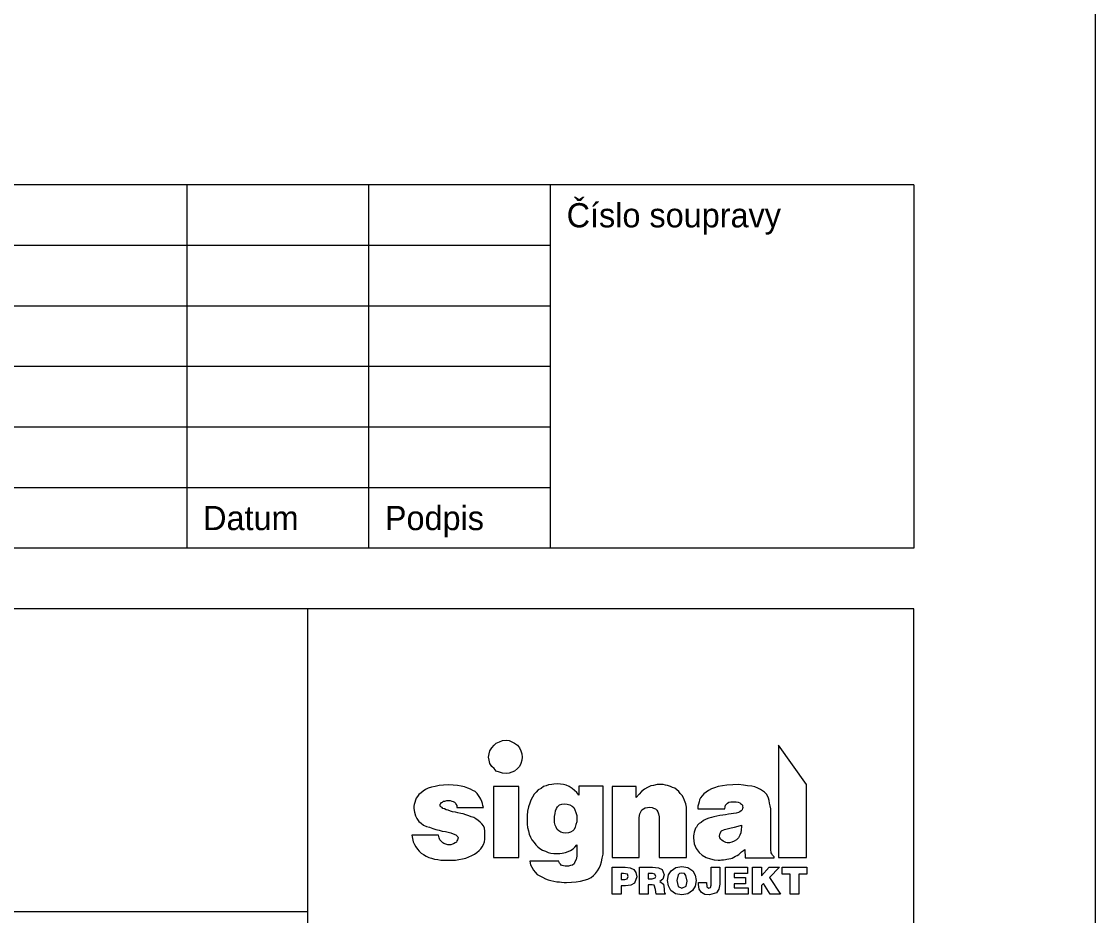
# Model space of a CAD drawing. Extents: x -790471 to -790261, y -984666 to -984369.
# Drawn here: x -790349.2 to -790260.6, y -984590.9 to -984517.1 of the extents above; entities that cross this region are included whole.
import ezdxf

# ---------------------------------------------------------------- set-up
doc = ezdxf.new("R2010")
doc.units = 0
for name, color, linetype in [('Info o rozpiskách', 7, 'Continuous'), ('popis', 7, 'Continuous'), ('Ramečky', 7, 'Continuous'), ('Rámečky-tisk', 7, 'Continuous'), ('Text', 7, 'Continuous')]:
    doc.layers.add(name, color=color, linetype=linetype)

msp = doc.modelspace()

# ---------------------------------------------------------------- linework, layer by layer
at = {"layer": 'Info o rozpiskách'}
for points in [[(-790309.246, -984576.456), (-790308.985, -984576.475), (-790308.761, -984576.568), (-790308.537, -984576.699), (-790308.294, -984576.867), (-790308.145, -984577.072), (-790308.033, -984577.315), (-790307.94, -984577.575), (-790307.921, -984577.837), (-790307.94, -984578.098), (-790308.033, -984578.378), (-790308.145, -984578.62), (-790308.294, -984578.788), (-790308.537, -984578.994), (-790308.761, -984579.087), (-790308.985, -984579.18), (-790309.246, -984579.199), (-790309.545, -984579.18), (-790309.787, -984579.087), (-790310.048, -984578.994), (-790310.235, -984578.788), (-790310.402, -984578.62), (-790310.571, -984578.378), (-790310.645, -984578.098), (-790310.701, -984577.837), (-790310.645, -984577.575), (-790310.571, -984577.315), (-790310.402, -984577.072), (-790310.235, -984576.867), (-790310.048, -984576.699), (-790309.787, -984576.568), (-790309.545, -984576.475), (-790309.246, -984576.456)], [(-790300.477, -984586.941), (-790299.414, -984586.941), (-790299.004, -984586.979), (-790298.705, -984587.128), (-790298.518, -984587.371), (-790298.462, -984587.725), (-790298.649, -984588.247), (-790298.948, -984588.416), (-790299.377, -984588.471), (-790299.75, -984588.471), (-790299.75, -984589.162), (-790300.477, -984589.162), (-790300.477, -984586.941)], [(-790299.75, -984587.445), (-790299.75, -984587.949), (-790299.432, -984587.949), (-790299.246, -984587.893), (-790299.153, -984587.688), (-790299.227, -984587.52), (-790299.545, -984587.445), (-790299.75, -984587.445)], [(-790298.238, -984586.941), (-790297.156, -984586.941), (-790296.672, -984586.979), (-790296.354, -984587.128), (-790296.186, -984587.576), (-790296.298, -984587.93), (-790296.559, -984588.117), (-790296.242, -984588.341), (-790296.186, -984588.714), (-790296.186, -984588.882), (-790296.168, -984589.05), (-790296.111, -984589.106), (-790296.111, -984589.162), (-790296.858, -984589.162), (-790296.896, -984588.769), (-790297.026, -984588.416), (-790297.175, -984588.396), (-790297.399, -984588.378), (-790297.511, -984588.378), (-790297.511, -984589.162), (-790298.238, -984589.162), (-790298.238, -984586.941)], [(-790297.511, -984587.445), (-790297.511, -984587.893), (-790297.194, -984587.893), (-790296.932, -984587.819), (-790296.876, -984587.688), (-790296.951, -984587.52), (-790297.156, -984587.445), (-790297.511, -984587.445)], [(-790294.731, -984586.885), (-790294.227, -984586.96), (-790293.835, -984587.221), (-790293.63, -984587.595), (-790293.556, -984588.023), (-790293.63, -984588.49), (-790293.854, -984588.863), (-790294.227, -984589.124), (-790294.731, -984589.217), (-790295.253, -984589.124), (-790295.645, -984588.844), (-790295.832, -984588.471), (-790295.907, -984588.023), (-790295.832, -984587.576), (-790295.608, -984587.221), (-790295.235, -984586.96), (-790294.731, -984586.885)], [(-790294.731, -984587.427), (-790294.918, -984587.464), (-790295.048, -984587.576), (-790295.16, -984588.042), (-790295.048, -984588.527), (-790294.731, -984588.676), (-790294.376, -984588.49), (-790294.283, -984588.079), (-790294.396, -984587.613), (-790294.525, -984587.464), (-790294.731, -984587.427)], [(-790292.325, -984586.941), (-790291.597, -984586.941), (-790291.597, -984588.322), (-790291.672, -984588.751), (-790291.877, -984589.05), (-790292.456, -984589.217), (-790292.829, -984589.18), (-790293.108, -984589.031), (-790293.295, -984588.751), (-790293.37, -984588.359), (-790293.351, -984588.192), (-790292.698, -984588.192), (-790292.661, -984588.565), (-790292.512, -984588.676), (-790292.381, -984588.602), (-790292.325, -984588.416), (-790292.325, -984586.941)], [(-790291.131, -984586.941), (-790289.321, -984586.941), (-790289.321, -984587.445), (-790290.404, -984587.445), (-790290.404, -984587.781), (-790289.489, -984587.781), (-790289.489, -984588.303), (-790290.404, -984588.303), (-790290.404, -984588.639), (-790289.266, -984588.639), (-790289.266, -984589.162), (-790291.131, -984589.162), (-790291.131, -984586.941)], [(-790288.911, -984586.941), (-790288.165, -984586.941), (-790288.165, -984587.651), (-790287.531, -984586.941), (-790286.672, -984586.941), (-790287.493, -984587.781), (-790286.579, -984589.162), (-790287.456, -984589.162), (-790287.997, -984588.285), (-790288.165, -984588.452), (-790288.165, -984589.162), (-790288.911, -984589.162), (-790288.911, -984586.941)], [(-790286.467, -984586.941), (-790284.414, -984586.941), (-790284.414, -984587.52), (-790285.068, -984587.52), (-790285.068, -984589.162), (-790285.796, -984589.162), (-790285.796, -984587.52), (-790286.467, -984587.52), (-790286.467, -984586.941)]]:
    msp.add_lwpolyline(points, dxfattribs=at)
at = {"layer": 'popis'}
for points in [[(-790286.765, -984576.867), (-790286.765, -984586.139), (-790284.452, -984586.139), (-790284.452, -984580.113), (-790286.765, -984576.867)], [(-790313.294, -984582.016), (-790311.093, -984582.016), (-790311.149, -984581.83), (-790311.187, -984581.661), (-790311.242, -984581.494), (-790311.316, -984581.326), (-790311.41, -984581.177), (-790311.522, -984581.009), (-790311.634, -984580.86), (-790311.802, -984580.691), (-790311.97, -984580.598), (-790312.175, -984580.486), (-790312.399, -984580.393), (-790312.66, -984580.299), (-790312.94, -984580.244), (-790313.257, -984580.188), (-790313.612, -984580.15), (-790314.003, -984580.132), (-790314.395, -984580.15), (-790314.768, -984580.188), (-790315.085, -984580.262), (-790315.402, -984580.319), (-790315.664, -984580.412), (-790315.888, -984580.523), (-790316.074, -984580.654), (-790316.261, -984580.785), (-790316.429, -984580.934), (-790316.541, -984581.084), (-790316.653, -984581.233), (-790316.709, -984581.4), (-790316.784, -984581.587), (-790316.82, -984581.755), (-790316.858, -984581.885), (-790316.858, -984582.091), (-790316.802, -984582.389), (-790316.709, -984582.688), (-790316.615, -984582.912), (-790316.429, -984583.154), (-790316.261, -984583.285), (-790316.056, -984583.453), (-790315.813, -984583.565), (-790315.552, -984583.639), (-790315.291, -984583.733), (-790315.029, -984583.807), (-790314.768, -984583.882), (-790314.507, -984583.957), (-790314.246, -984583.993), (-790314.022, -984584.031), (-790313.798, -984584.087), (-790313.593, -984584.181), (-790313.388, -984584.255), (-790313.294, -984584.33), (-790313.22, -984584.423), (-790313.201, -984584.516), (-790313.239, -984584.684), (-790313.294, -984584.758), (-790313.332, -984584.852), (-790313.444, -984584.927), (-790313.574, -984585.001), (-790313.667, -984585.038), (-790313.798, -984585.076), (-790313.929, -984585.076), (-790314.06, -984585.076), (-790314.209, -984585.038), (-790314.377, -984584.982), (-790314.47, -984584.927), (-790314.601, -984584.796), (-790314.694, -984584.684), (-790314.768, -984584.498), (-790314.825, -984584.274), (-790317.007, -984584.274), (-790316.97, -984584.572), (-790316.895, -984584.833), (-790316.802, -984585.057), (-790316.69, -984585.244), (-790316.56, -984585.43), (-790316.41, -984585.598), (-790316.242, -984585.766), (-790316.056, -984585.896), (-790315.832, -984586.009), (-790315.608, -984586.12), (-790315.384, -984586.195), (-790315.142, -984586.269), (-790314.861, -984586.289), (-790314.619, -984586.344), (-790314.377, -984586.363), (-790314.06, -984586.363), (-790313.742, -984586.344), (-790313.425, -984586.344), (-790313.126, -984586.289), (-790312.828, -984586.233), (-790312.549, -984586.176), (-790312.306, -984586.083), (-790312.063, -984585.953), (-790311.858, -984585.859), (-790311.653, -984585.729), (-790311.466, -984585.561), (-790311.336, -984585.412), (-790311.205, -984585.244), (-790311.093, -984585.057), (-790311.018, -984584.833), (-790310.999, -984584.609), (-790310.999, -984584.385), (-790310.999, -984584.33), (-790310.999, -984584.274), (-790310.999, -984584.217), (-790310.999, -984584.161), (-790310.999, -984584.087), (-790310.999, -984584.031), (-790310.999, -984583.993), (-790310.999, -984583.957), (-790311.018, -984583.714), (-790311.112, -984583.527), (-790311.242, -984583.341), (-790311.391, -984583.21), (-790311.54, -984583.079), (-790311.727, -984582.93), (-790311.895, -984582.837), (-790312.119, -984582.762), (-790312.325, -984582.688), (-790312.549, -984582.613), (-790312.772, -984582.538), (-790312.977, -984582.501), (-790313.22, -984582.445), (-790313.425, -984582.389), (-790313.649, -984582.352), (-790313.836, -984582.296), (-790314.022, -984582.222), (-790314.19, -984582.184), (-790314.32, -984582.109), (-790314.451, -984582.072), (-790314.526, -984582.016), (-790314.637, -984581.941), (-790314.675, -984581.885), (-790314.675, -984581.811), (-790314.675, -984581.736), (-790314.637, -984581.661), (-790314.563, -984581.587), (-790314.488, -984581.55), (-790314.414, -984581.475), (-790314.283, -984581.475), (-790314.134, -984581.437), (-790314.003, -984581.437), (-790313.854, -984581.437), (-790313.723, -984581.475), (-790313.612, -984581.494), (-790313.499, -984581.55), (-790313.425, -984581.643), (-790313.388, -984581.736), (-790313.313, -984581.848), (-790313.294, -984582.016)], [(-790310.272, -984580.262), (-790310.272, -984586.139), (-790308.183, -984586.139), (-790308.183, -984580.262), (-790310.272, -984580.262)], [(-790303.239, -984580.244), (-790303.239, -984580.971), (-790303.407, -984580.766), (-790303.593, -984580.598), (-790303.798, -984580.43), (-790304.041, -984580.281), (-790304.283, -984580.169), (-790304.507, -984580.113), (-790304.75, -984580.075), (-790305.029, -984580.057), (-790305.291, -984580.075), (-790305.477, -984580.095), (-790305.739, -984580.132), (-790305.925, -984580.225), (-790306.149, -984580.281), (-790306.354, -984580.43), (-790306.578, -984580.542), (-790306.764, -984580.729), (-790306.914, -984580.915), (-790307.063, -984581.158), (-790307.194, -984581.4), (-790307.287, -984581.643), (-790307.399, -984581.96), (-790307.474, -984582.296), (-790307.511, -984582.669), (-790307.511, -984583.061), (-790307.511, -984583.378), (-790307.474, -984583.658), (-790307.399, -984583.919), (-790307.325, -984584.199), (-790307.231, -984584.441), (-790307.101, -984584.684), (-790306.932, -984584.889), (-790306.783, -984585.076), (-790306.615, -984585.244), (-790306.447, -984585.393), (-790306.224, -984585.523), (-790306, -984585.617), (-790305.776, -984585.71), (-790305.533, -984585.766), (-790305.291, -984585.803), (-790305.029, -984585.803), (-790304.805, -984585.803), (-790304.601, -984585.766), (-790304.339, -984585.729), (-790304.115, -984585.636), (-790303.91, -984585.543), (-790303.705, -984585.412), (-790303.556, -984585.281), (-790303.388, -984585.095), (-790303.388, -984585.636), (-790303.388, -984586.027), (-790303.462, -984586.289), (-790303.556, -984586.493), (-790303.631, -984586.643), (-790303.761, -984586.755), (-790303.91, -984586.792), (-790304.078, -984586.848), (-790304.264, -984586.848), (-790304.358, -984586.848), (-790304.488, -984586.83), (-790304.601, -984586.792), (-790304.694, -984586.755), (-790304.75, -984586.681), (-790304.843, -984586.606), (-790304.862, -984586.531), (-790304.899, -984586.438), (-790307.268, -984586.438), (-790307.212, -984586.736), (-790307.101, -984586.941), (-790306.97, -984587.165), (-790306.839, -984587.333), (-790306.671, -984587.538), (-790306.447, -984587.651), (-790306.242, -984587.744), (-790306, -984587.893), (-790305.776, -984587.968), (-790305.533, -984588.023), (-790305.309, -984588.079), (-790305.048, -984588.135), (-790304.843, -984588.154), (-790304.656, -984588.173), (-790304.432, -984588.192), (-790304.264, -984588.192), (-790303.854, -984588.173), (-790303.462, -984588.135), (-790303.089, -984588.079), (-790302.791, -984588.005), (-790302.493, -984587.912), (-790302.231, -984587.781), (-790302.026, -984587.631), (-790301.858, -984587.445), (-790301.69, -984587.24), (-790301.559, -984587.016), (-790301.448, -984586.774), (-790301.355, -984586.493), (-790301.317, -984586.195), (-790301.224, -984585.859), (-790301.224, -984585.505), (-790301.224, -984585.095), (-790301.224, -984580.244), (-790303.239, -984580.244)], [(-790300.496, -984580.262), (-790300.496, -984586.139), (-790298.257, -984586.139), (-790298.257, -984583.136), (-790298.257, -984582.819), (-790298.201, -984582.52), (-790298.108, -984582.352), (-790298.034, -984582.203), (-790297.903, -984582.109), (-790297.753, -984582.034), (-790297.567, -984582.016), (-790297.38, -984581.979), (-790297.194, -984582.016), (-790297.063, -984582.054), (-790296.896, -984582.109), (-790296.802, -984582.222), (-790296.727, -984582.352), (-790296.653, -984582.52), (-790296.615, -984582.781), (-790296.615, -984583.043), (-790296.615, -984586.139), (-790294.339, -984586.139), (-790294.339, -984582.595), (-790294.339, -984582.277), (-790294.358, -984581.979), (-790294.414, -984581.699), (-790294.507, -984581.437), (-790294.6, -984581.214), (-790294.713, -984581.009), (-790294.88, -984580.841), (-790294.992, -984580.672), (-790295.141, -984580.542), (-790295.31, -984580.412), (-790295.496, -984580.356), (-790295.683, -984580.262), (-790295.907, -984580.188), (-790296.093, -984580.15), (-790296.28, -984580.113), (-790296.504, -984580.113), (-790296.783, -984580.113), (-790297.063, -984580.188), (-790297.306, -984580.225), (-790297.567, -984580.356), (-790297.81, -984580.486), (-790298.052, -984580.672), (-790298.257, -984580.915), (-790298.5, -984581.177), (-790298.5, -984580.262), (-790300.496, -984580.262)], [(-790293.407, -984582.109), (-790291.187, -984582.109), (-790291.169, -984581.941), (-790291.131, -984581.811), (-790291.056, -984581.717), (-790290.963, -984581.643), (-790290.851, -984581.568), (-790290.702, -984581.531), (-790290.572, -984581.531), (-790290.422, -984581.531), (-790290.254, -984581.531), (-790290.086, -984581.55), (-790289.956, -984581.624), (-790289.881, -984581.661), (-790289.807, -984581.736), (-790289.732, -984581.811), (-790289.732, -984581.904), (-790289.694, -984581.998), (-790289.732, -984582.091), (-790289.75, -984582.203), (-790289.844, -984582.277), (-790289.937, -984582.352), (-790290.067, -984582.427), (-790290.254, -984582.464), (-790290.459, -984582.501), (-790290.665, -984582.538), (-790290.889, -984582.557), (-790291.131, -984582.595), (-790291.355, -984582.632), (-790291.597, -984582.669), (-790291.84, -984582.725), (-790292.083, -984582.762), (-790292.288, -984582.837), (-790292.512, -984582.874), (-790292.735, -984582.968), (-790292.959, -984583.079), (-790293.146, -984583.229), (-790293.314, -984583.322), (-790293.445, -984583.471), (-790293.537, -984583.62), (-790293.611, -984583.714), (-790293.668, -984583.882), (-790293.705, -984584.031), (-790293.742, -984584.199), (-790293.761, -984584.348), (-790293.761, -984584.516), (-790293.705, -984585.001), (-790293.556, -984585.393), (-790293.314, -984585.729), (-790293.053, -984585.934), (-790292.735, -984586.12), (-790292.381, -984586.251), (-790292.064, -984586.326), (-790291.728, -984586.344), (-790291.579, -984586.344), (-790291.448, -984586.326), (-790291.299, -984586.326), (-790291.131, -984586.289), (-790291.019, -984586.269), (-790290.851, -984586.251), (-790290.702, -984586.214), (-790290.572, -984586.176), (-790290.441, -984586.102), (-790290.31, -984586.027), (-790290.18, -984585.971), (-790290.031, -984585.878), (-790289.918, -984585.785), (-790289.807, -984585.673), (-790289.657, -984585.561), (-790289.545, -984585.468), (-790289.508, -984586.158), (-790287.12, -984586.158), (-790287.12, -984586.065), (-790287.251, -984585.934), (-790287.307, -984585.841), (-790287.362, -984585.747), (-790287.362, -984585.673), (-790287.4, -984585.561), (-790287.4, -984585.486), (-790287.4, -984585.374), (-790287.4, -984585.225), (-790287.4, -984582.352), (-790287.4, -984582.109), (-790287.456, -984581.867), (-790287.493, -984581.643), (-790287.531, -984581.419), (-790287.586, -984581.233), (-790287.642, -984581.084), (-790287.735, -984580.915), (-790287.904, -984580.747), (-790288.072, -984580.617), (-790288.239, -984580.505), (-790288.463, -984580.393), (-790288.706, -984580.299), (-790288.967, -984580.244), (-790289.303, -984580.206), (-790289.657, -984580.169), (-790290.067, -984580.113), (-790290.534, -984580.132), (-790291.019, -984580.169), (-790291.373, -984580.225), (-790291.728, -984580.281), (-790292.045, -984580.374), (-790292.288, -984580.468), (-790292.531, -984580.598), (-790292.735, -984580.729), (-790292.922, -984580.878), (-790293.053, -984581.027), (-790293.202, -984581.195), (-790293.277, -984581.382), (-790293.314, -984581.531), (-790293.37, -984581.717), (-790293.407, -984581.904), (-790293.407, -984582.109)], [(-790304.395, -984581.699), (-790304.19, -984581.736), (-790303.985, -984581.792), (-790303.798, -984581.885), (-790303.649, -984582.016), (-790303.556, -984582.203), (-790303.481, -984582.408), (-790303.407, -984582.669), (-790303.407, -984582.949), (-790303.407, -984583.192), (-790303.481, -984583.415), (-790303.537, -984583.639), (-790303.631, -984583.807), (-790303.742, -984583.919), (-790303.91, -984584.05), (-790304.078, -984584.106), (-790304.302, -984584.124), (-790304.526, -984584.106), (-790304.712, -984584.05), (-790304.899, -984583.919), (-790305.011, -984583.826), (-790305.104, -984583.639), (-790305.197, -984583.471), (-790305.235, -984583.247), (-790305.253, -984583.005), (-790305.235, -984582.744), (-790305.197, -984582.501), (-790305.16, -984582.277), (-790305.086, -984582.072), (-790304.992, -984581.941), (-790304.824, -984581.792), (-790304.638, -984581.736), (-790304.395, -984581.699)], [(-790289.807, -984583.471), (-790289.807, -984583.49), (-790289.807, -984583.546), (-790289.807, -984583.583), (-790289.844, -984583.844), (-790289.862, -984584.106), (-790289.956, -984584.292), (-790290.067, -984584.516), (-790290.217, -984584.684), (-790290.404, -984584.777), (-790290.608, -984584.871), (-790290.814, -984584.927), (-790290.982, -984584.927), (-790291.094, -984584.889), (-790291.205, -984584.833), (-790291.318, -984584.777), (-790291.429, -984584.703), (-790291.523, -984584.609), (-790291.597, -984584.516), (-790291.616, -984584.367), (-790291.579, -984584.124), (-790291.448, -984583.938), (-790291.224, -984583.826), (-790290.982, -984583.751), (-790290.665, -984583.677), (-790290.384, -984583.639), (-790290.086, -984583.546), (-790289.807, -984583.471)]]:
    msp.add_lwpolyline(points, dxfattribs=at)
at = {"layer": 'Ramečky'}
for p, q in [((-790275.592, -984530.601), (-790455.592, -984530.601)), ((-790335.592, -984530.601), (-790335.592, -984560.601)), ((-790320.592, -984530.601), (-790320.592, -984560.601)), ((-790305.592, -984530.601), (-790305.592, -984560.601)), ((-790275.592, -984530.601), (-790275.592, -984560.601)), ((-790305.592, -984535.601), (-790455.592, -984535.601)), ((-790305.592, -984540.601), (-790455.592, -984540.601)), ((-790305.592, -984545.601), (-790455.592, -984545.601)), ((-790305.592, -984550.601), (-790455.592, -984550.601)), ((-790305.592, -984555.601), (-790455.592, -984555.601)), ((-790275.592, -984560.601), (-790455.592, -984560.601)), ((-790275.592, -984565.601), (-790455.592, -984565.601)), ((-790325.592, -984650.601), (-790325.592, -984565.601)), ((-790275.592, -984650.601), (-790275.592, -984565.601)), ((-790455.592, -984590.601), (-790325.592, -984590.601))]:
    msp.add_line(p, q, dxfattribs=at)
at = {"layer": 'Rámečky-tisk'}
msp.add_lwpolyline([(-790470.592, -984665.601), (-790260.592, -984665.601), (-790260.592, -984368.601)], dxfattribs=at)

# ---------------------------------------------------------------- texts
at = {"layer": 'Text'}
for s, p in [('Číslo soupravy', (-790304.242, -984534.101)), ('Datum', (-790334.242, -984559.101)), ('Podpis', (-790319.242, -984559.101))]:
    msp.add_text(s, height=2, dxfattribs=at).set_placement(p)

doc.saveas('drawing.dxf')
